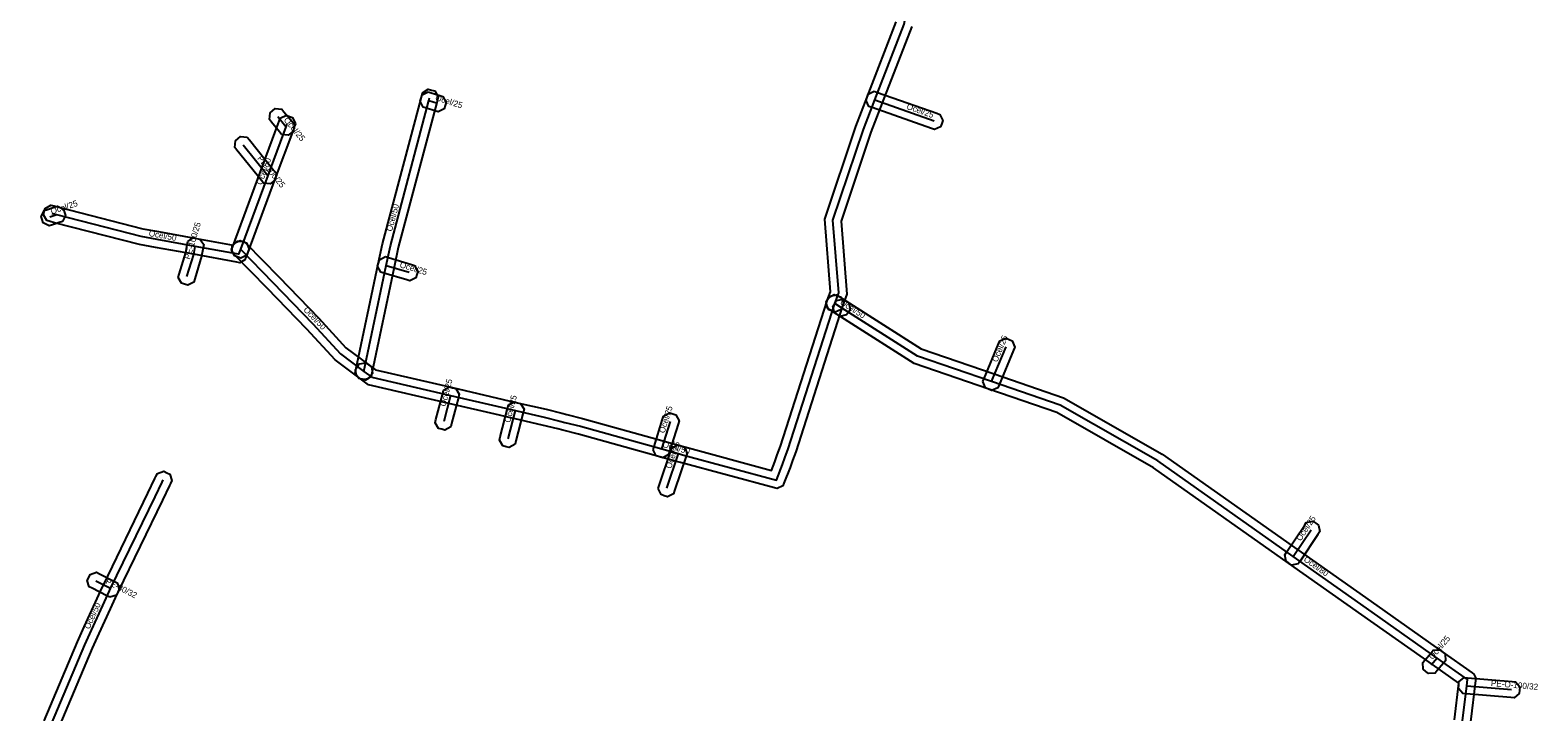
# Model space of a CAD drawing. Extents: x -569373 to -565022, y -1135090 to -1131496.
# Drawn here: x -565423.2 to -565236.8, y -1133846.6 to -1133762.4 of the extents above; entities that cross this region are included whole.
import ezdxf

# ---------------------------------------------------------------- set-up
doc = ezdxf.new("R2010")
doc.units = 0
for name, color, linetype in [('1', 7, 'Continuous'), ('24', 7, 'Continuous'), ('30', 7, 'Continuous')]:
    doc.layers.add(name, color=color, linetype=linetype)

msp = doc.modelspace()

# ---------------------------------------------------------------- linework, layer by layer
at = {"layer": '1'}
for points in [[(-565314.174, -1133761.894), (-565317.838, -1133771.351), (-565319.239, -1133774.97), (-565322.927, -1133785.974), (-565322.216, -1133794.98), (-565322.772, -1133796.486), (-565322.915, -1133796.875), (-565323.667, -1133797.221), (-565324.056, -1133797.078), (-565324.445, -1133796.935), (-565324.791, -1133796.183), (-565324.648, -1133795.794), (-565324.244, -1133794.7), (-565324.953, -1133785.726), (-565321.121, -1133774.29), (-565319.702, -1133770.629), (-565316.106, -1133761.346)], [(-565247.112, -1133847.641), (-565246.573, -1133843.104), (-565249.827, -1133840.807), (-565258.586, -1133834.627), (-565267.617, -1133828.257), (-565284.337, -1133816.455), (-565296.284, -1133809.645), (-565304.656, -1133806.755), (-565313.917, -1133803.567), (-565323.407, -1133797.523), (-565323.757, -1133797.301), (-565323.936, -1133796.492), (-565323.713, -1133796.143), (-565323.491, -1133795.793), (-565322.682, -1133795.614), (-565322.333, -1133795.837), (-565313.043, -1133801.753), (-565304.004, -1133804.865), (-565295.456, -1133807.815), (-565283.263, -1133814.765), (-565266.463, -1133826.623), (-565257.434, -1133832.993), (-565248.673, -1133839.173), (-565244.933, -1133841.813), (-565244.708, -1133841.972), (-565244.485, -1133842.474), (-565244.517, -1133842.748), (-565245.126, -1133847.877)], [(-565421.442, -1133847.742), (-565417.316, -1133837.968), (-565416.48, -1133836.135), (-565415.08, -1133833.075), (-565414.246, -1133831.246), (-565414.111, -1133830.965), (-565408.61, -1133819.605), (-565407.741, -1133817.806), (-565407.611, -1133817.536), (-565407.431, -1133817.163), (-565406.649, -1133816.889), (-565406.276, -1133817.069), (-565405.903, -1133817.249), (-565405.629, -1133818.031), (-565405.809, -1133818.404), (-565405.939, -1133818.674), (-565406.81, -1133820.475), (-565412.309, -1133831.835), (-565412.434, -1133832.094), (-565413.26, -1133833.905), (-565414.66, -1133836.965), (-565415.484, -1133838.772), (-565419.598, -1133848.518)]]:
    msp.add_lwpolyline(points, dxfattribs=at)
for points in [[(-565382.974, -1133804.75), (-565382.889, -1133804.344), (-565380.129, -1133791.234), (-565379.613, -1133788.779), (-565374.847, -1133770.797), (-565374.768, -1133770.49), (-565374.664, -1133770.089), (-565373.951, -1133769.668), (-565373.55, -1133769.772), (-565373.149, -1133769.876), (-565372.728, -1133770.589), (-565372.832, -1133770.99), (-565372.913, -1133771.303), (-565377.667, -1133789.241), (-565378.171, -1133791.646), (-565380.931, -1133804.756), (-565381.016, -1133805.162), (-565381.71, -1133805.614), (-565382.116, -1133805.529), (-565382.522, -1133805.444)], [(-565373.975, -1133769.972), (-565373.58, -1133770.096), (-565372.53, -1133770.426), (-565372.135, -1133770.55), (-565371.752, -1133771.285), (-565371.876, -1133771.68), (-565372, -1133772.075), (-565372.735, -1133772.458), (-565373.13, -1133772.334), (-565374.18, -1133772.004), (-565374.575, -1133771.88), (-565374.958, -1133771.145), (-565374.834, -1133770.75), (-565374.71, -1133770.355)], [(-565318.828, -1133769.909), (-565318.437, -1133770.047), (-565311.107, -1133772.637), (-565310.716, -1133772.775), (-565310.359, -1133773.522), (-565310.497, -1133773.913), (-565310.635, -1133774.304), (-565311.382, -1133774.661), (-565311.773, -1133774.523), (-565319.103, -1133771.933), (-565319.494, -1133771.795), (-565319.851, -1133771.048), (-565319.713, -1133770.657), (-565319.575, -1133770.266)], [(-565390.368, -1133773.923), (-565390.51, -1133774.312), (-565390.631, -1133774.645), (-565392.862, -1133780.667), (-565396.242, -1133789.797), (-565396.386, -1133790.186), (-565397.138, -1133790.532), (-565397.527, -1133790.388), (-565397.916, -1133790.244), (-565398.262, -1133789.492), (-565398.118, -1133789.103), (-565394.738, -1133779.973), (-565392.509, -1133773.955), (-565392.39, -1133773.628), (-565392.248, -1133773.239), (-565391.497, -1133772.888), (-565391.108, -1133773.03), (-565390.719, -1133773.172)], [(-565392.082, -1133775.254), (-565392.344, -1133774.933), (-565393.334, -1133773.723), (-565393.596, -1133773.402), (-565393.514, -1133772.578), (-565393.193, -1133772.316), (-565392.872, -1133772.054), (-565392.048, -1133772.136), (-565391.786, -1133772.457), (-565390.796, -1133773.667), (-565390.534, -1133773.988), (-565390.616, -1133774.812), (-565390.937, -1133775.074), (-565391.258, -1133775.336)], [(-565396.322, -1133775.6), (-565396.062, -1133775.922), (-565393.022, -1133779.692), (-565392.762, -1133780.015), (-565392.85, -1133780.838), (-565393.172, -1133781.098), (-565393.495, -1133781.358), (-565394.318, -1133781.27), (-565394.578, -1133780.948), (-565397.618, -1133777.178), (-565397.878, -1133776.855), (-565397.79, -1133776.032), (-565397.468, -1133775.772), (-565397.145, -1133775.512)], [(-565419.177, -1133786.023), (-565419.571, -1133786.151), (-565420.401, -1133786.421), (-565420.795, -1133786.549), (-565421.533, -1133786.173), (-565421.661, -1133785.779), (-565421.789, -1133785.385), (-565421.413, -1133784.647), (-565421.019, -1133784.519), (-565420.189, -1133784.249), (-565419.795, -1133784.121), (-565419.057, -1133784.497), (-565418.929, -1133784.891), (-565418.801, -1133785.285)], [(-565402.591, -1133788.106), (-565398.054, -1133788.937), (-565397.963, -1133788.703), (-565397.205, -1133788.367), (-565396.819, -1133788.517), (-565396.433, -1133788.667), (-565396.097, -1133789.425), (-565396.247, -1133789.811), (-565396.487, -1133790.431), (-565396.617, -1133790.767), (-565397.246, -1133791.119), (-565397.6, -1133791.054), (-565402.949, -1133790.074), (-565407.648, -1133789.221), (-565409.654, -1133788.858), (-565420.132, -1133786.168), (-565420.704, -1133786.017), (-565421.105, -1133785.912), (-565421.523, -1133785.197), (-565421.417, -1133784.796), (-565421.312, -1133784.395), (-565420.597, -1133783.977), (-565420.196, -1133784.083), (-565419.628, -1133784.232), (-565409.226, -1133786.902), (-565407.292, -1133787.253)], [(-565404.857, -1133792.926), (-565404.737, -1133792.53), (-565403.924, -1133789.845), (-565403.754, -1133788.911), (-565403.68, -1133788.503), (-565402.999, -1133788.032), (-565402.591, -1133788.106), (-565402.183, -1133788.18), (-565401.712, -1133788.861), (-565401.786, -1133789.269), (-565401.976, -1133790.315), (-565402.823, -1133793.11), (-565402.943, -1133793.506), (-565403.674, -1133793.897), (-565404.07, -1133793.777), (-565404.466, -1133793.657)], [(-565396.756, -1133788.454), (-565396.466, -1133788.75), (-565392.443, -1133792.852), (-565387.493, -1133797.973), (-565384.126, -1133801.616), (-565381.306, -1133803.753), (-565380.976, -1133804.003), (-565380.863, -1133804.824), (-565381.113, -1133805.154), (-565381.363, -1133805.484), (-565382.184, -1133805.597), (-565382.514, -1133805.347), (-565385.474, -1133803.104), (-565388.947, -1133799.347), (-565393.877, -1133794.248), (-565397.894, -1133790.15), (-565398.184, -1133789.854), (-565398.176, -1133789.026), (-565397.88, -1133788.736), (-565397.584, -1133788.446)], [(-565379.258, -1133790.363), (-565378.861, -1133790.483), (-565376.041, -1133791.333), (-565375.645, -1133791.452), (-565375.253, -1133792.182), (-565375.373, -1133792.579), (-565375.492, -1133792.975), (-565376.222, -1133793.367), (-565376.619, -1133793.247), (-565379.439, -1133792.397), (-565379.835, -1133792.278), (-565380.227, -1133791.548), (-565380.107, -1133791.151), (-565379.988, -1133790.755)], [(-565381.657, -1133803.497), (-565381.322, -1133803.741), (-565380.496, -1133804.342), (-565370.973, -1133806.556), (-565364.715, -1133808.016), (-565362.967, -1133808.415), (-565362.765, -1133808.461), (-565359.397, -1133809.237), (-565357.449, -1133809.722), (-565356.827, -1133809.877), (-565354.874, -1133810.363), (-565344.812, -1133813.177), (-565342.752, -1133813.747), (-565342.255, -1133813.886), (-565331.52, -1133816.782), (-565331.1, -1133815.728), (-565330.822, -1133814.882), (-565330.403, -1133813.806), (-565324.663, -1133795.836), (-565324.537, -1133795.441), (-565323.8, -1133795.061), (-565323.406, -1133795.187), (-565323.011, -1133795.313), (-565322.631, -1133796.05), (-565322.757, -1133796.444), (-565328.517, -1133814.474), (-565328.938, -1133815.558), (-565329.22, -1133816.412), (-565329.991, -1133818.35), (-565330.132, -1133818.704), (-565330.813, -1133819.045), (-565331.181, -1133818.945), (-565342.785, -1133815.814), (-565343.288, -1133815.673), (-565345.348, -1133815.103), (-565355.386, -1133812.297), (-565357.311, -1133811.817), (-565357.933, -1133811.662), (-565359.863, -1133811.183), (-565363.213, -1133810.411), (-565363.413, -1133810.365), (-565365.165, -1133809.964), (-565371.427, -1133808.504), (-565381.344, -1133806.198), (-565382.498, -1133805.359), (-565382.833, -1133805.115), (-565382.963, -1133804.297), (-565382.719, -1133803.962), (-565382.475, -1133803.627)], [(-565323.063, -1133797.745), (-565323.411, -1133797.521), (-565324.251, -1133796.981), (-565324.599, -1133796.757), (-565324.775, -1133795.947), (-565324.551, -1133795.599), (-565324.327, -1133795.251), (-565323.517, -1133795.075), (-565323.169, -1133795.299), (-565322.329, -1133795.839), (-565321.981, -1133796.063), (-565321.805, -1133796.873), (-565322.029, -1133797.221), (-565322.253, -1133797.569)], [(-565305.412, -1133805.806), (-565305.253, -1133805.424), (-565303.463, -1133801.144), (-565303.303, -1133800.762), (-565302.536, -1133800.448), (-565302.154, -1133800.607), (-565301.772, -1133800.767), (-565301.458, -1133801.534), (-565301.617, -1133801.916), (-565303.407, -1133806.196), (-565303.567, -1133806.578), (-565304.334, -1133806.892), (-565304.716, -1133806.733), (-565305.098, -1133806.573)], [(-565370.128, -1133807.382), (-565370.233, -1133807.783), (-565371.073, -1133810.993), (-565371.178, -1133811.394), (-565371.892, -1133811.812), (-565372.293, -1133811.707), (-565372.694, -1133811.602), (-565373.112, -1133810.888), (-565373.007, -1133810.487), (-565372.167, -1133807.277), (-565372.062, -1133806.876), (-565371.348, -1133806.458), (-565370.947, -1133806.563), (-565370.546, -1133806.668)], [(-565365.162, -1133813.042), (-565365.058, -1133812.641), (-565364.158, -1133809.141), (-565364.055, -1133808.74), (-565363.342, -1133808.318), (-565362.941, -1133808.422), (-565362.54, -1133808.525), (-565362.118, -1133809.238), (-565362.222, -1133809.639), (-565363.122, -1133813.139), (-565363.225, -1133813.54), (-565363.938, -1133813.962), (-565364.339, -1133813.858), (-565364.74, -1133813.755)], [(-565346.158, -1133814.239), (-565346.035, -1133813.843), (-565344.985, -1133810.463), (-565344.862, -1133810.067), (-565344.129, -1133809.682), (-565343.733, -1133809.805), (-565343.337, -1133809.928), (-565342.952, -1133810.661), (-565343.075, -1133811.057), (-565344.125, -1133814.437), (-565344.248, -1133814.833), (-565344.981, -1133815.218), (-565345.377, -1133815.095), (-565345.773, -1133814.972)], [(-565345.55, -1133819.04), (-565345.417, -1133818.648), (-565343.967, -1133814.388), (-565343.833, -1133813.996), (-565343.09, -1133813.63), (-565342.698, -1133813.763), (-565342.306, -1133813.897), (-565341.94, -1133814.64), (-565342.073, -1133815.032), (-565343.523, -1133819.292), (-565343.657, -1133819.684), (-565344.4, -1133820.05), (-565344.792, -1133819.917), (-565345.184, -1133819.783)], [(-565268.101, -1133827.228), (-565267.871, -1133826.884), (-565265.661, -1133823.584), (-565265.43, -1133823.24), (-565264.618, -1133823.079), (-565264.274, -1133823.309), (-565263.93, -1133823.54), (-565263.769, -1133824.352), (-565263.999, -1133824.696), (-565266.209, -1133827.996), (-565266.44, -1133828.34), (-565267.252, -1133828.501), (-565267.596, -1133828.271), (-565267.94, -1133828.04)], [(-565413.296, -1133832.479), (-565413.665, -1133832.29), (-565415.485, -1133831.36), (-565415.854, -1133831.172), (-565416.109, -1133830.384), (-565415.92, -1133830.015), (-565415.732, -1133829.646), (-565414.944, -1133829.391), (-565414.575, -1133829.58), (-565412.755, -1133830.51), (-565412.386, -1133830.698), (-565412.131, -1133831.486), (-565412.32, -1133831.855), (-565412.508, -1133832.224)], [(-565248.221, -1133840.324), (-565248.49, -1133840.639), (-565249.25, -1133841.529), (-565249.519, -1133841.844), (-565250.344, -1133841.909), (-565250.659, -1133841.64), (-565250.974, -1133841.371), (-565251.039, -1133840.546), (-565250.77, -1133840.231), (-565250.01, -1133839.341), (-565249.741, -1133839.026), (-565248.916, -1133838.961), (-565248.601, -1133839.23), (-565248.286, -1133839.499)], [(-565245.932, -1133842.383), (-565245.519, -1133842.418), (-565239.996, -1133842.884), (-565239.583, -1133842.919), (-565239.049, -1133843.551), (-565239.084, -1133843.964), (-565239.119, -1133844.377), (-565239.751, -1133844.911), (-565240.164, -1133844.876), (-565245.687, -1133844.41), (-565246.1, -1133844.375), (-565246.634, -1133843.743), (-565246.599, -1133843.33), (-565246.564, -1133842.917)]]:
    msp.add_lwpolyline(points, close=True, dxfattribs=at)
at = {"layer": '24'}
for points in [[(-565323.71, -1133796.14), (-565323.23, -1133794.84), (-565323.94, -1133785.85), (-565320.18, -1133774.63), (-565318.77, -1133770.99), (-565315.14, -1133761.62), (-565314.25, -1133756.83), (-565312.98, -1133750.01), (-565321.88, -1133740.73), (-565331.07, -1133737.1), (-565335.14, -1133735.5), (-565338.77, -1133734.06), (-565340.3, -1133733.46), (-565351.18, -1133729.27)], [(-565381.91, -1133804.55), (-565379.15, -1133791.44), (-565378.64, -1133789.01), (-565373.88, -1133771.05), (-565373.8, -1133770.74)], [(-565373.88, -1133771.05), (-565372.83, -1133771.38)], [(-565318.77, -1133770.99), (-565311.44, -1133773.58)], [(-565391.45, -1133773.97), (-565391.57, -1133774.3), (-565393.8, -1133780.32), (-565397.18, -1133789.45)], [(-565391.57, -1133774.3), (-565392.56, -1133773.09)], [(-565396.84, -1133776.55), (-565393.8, -1133780.32)], [(-565419.88, -1133785.2), (-565420.71, -1133785.47)], [(-565397.18, -1133789.45), (-565397.42, -1133790.07), (-565402.77, -1133789.09), (-565407.47, -1133788.237), (-565409.44, -1133787.88), (-565419.88, -1133785.2), (-565420.45, -1133785.05)], [(-565403.78, -1133792.82), (-565402.95, -1133790.08), (-565402.77, -1133789.09)], [(-565397.18, -1133789.45), (-565393.16, -1133793.55), (-565388.22, -1133798.66), (-565384.8, -1133802.36), (-565381.91, -1133804.55)], [(-565379.15, -1133791.44), (-565376.33, -1133792.29)], [(-565381.91, -1133804.55), (-565380.92, -1133805.27), (-565371.2, -1133807.53), (-565364.94, -1133808.99), (-565363.19, -1133809.39), (-565362.989, -1133809.436), (-565359.63, -1133810.21), (-565357.691, -1133810.692), (-565357.069, -1133810.847), (-565355.13, -1133811.33), (-565345.08, -1133814.14), (-565343.02, -1133814.71), (-565342.52, -1133814.85), (-565330.92, -1133817.98), (-565330.16, -1133816.07), (-565329.88, -1133815.22), (-565329.46, -1133814.14), (-565323.71, -1133796.14)], [(-565322.87, -1133796.68), (-565323.71, -1133796.14)], [(-565250.86, -1133882.66), (-565250.236, -1133878.181), (-565249.96, -1133876.2), (-565249.87, -1133875.59), (-565247.48, -1133859.22), (-565246.119, -1133847.759), (-565245.603, -1133843.414), (-565245.51, -1133842.63), (-565249.25, -1133839.99), (-565258.01, -1133833.81), (-565267.04, -1133827.44), (-565283.8, -1133815.61), (-565295.87, -1133808.73), (-565304.33, -1133805.81), (-565313.48, -1133802.66), (-565322.87, -1133796.68)], [(-565304.33, -1133805.81), (-565302.54, -1133801.53)], [(-565371.2, -1133807.53), (-565372.04, -1133810.74)], [(-565364.09, -1133812.89), (-565363.19, -1133809.39)], [(-565345.08, -1133814.14), (-565344.03, -1133810.76)], [(-565344.47, -1133818.97), (-565343.02, -1133814.71)], [(-565422.03, -1133855.52), (-565423.16, -1133854.41), (-565421.294, -1133849.972), (-565420.52, -1133848.13), (-565416.4, -1133838.37), (-565415.57, -1133836.55), (-565414.17, -1133833.49), (-565413.34, -1133831.67), (-565413.21, -1133831.4), (-565407.71, -1133820.04), (-565406.84, -1133818.24), (-565406.71, -1133817.97)], [(-565267.04, -1133827.44), (-565264.83, -1133824.14)], [(-565413.21, -1133831.4), (-565415.03, -1133830.47)], [(-565249.25, -1133839.99), (-565250.01, -1133840.88)], [(-565245.603, -1133843.414), (-565240.08, -1133843.88)]]:
    msp.add_lwpolyline(points, dxfattribs=at)

# ---------------------------------------------------------------- texts
at = {"layer": '30'}
for s, rotation, p in [('Ocel/25', 342.55281, (-565373.155, -1133771.015)), ('Ocel/25', 340.53952, (-565314.905, -1133772.085)), ('Ocel/25', 309.28941, (-565391.865, -1133773.495)), ('Ocel/50', 69.68504, (-565394.532, -1133781.557)), ('PE-100/25', 308.88153, (-565395.12, -1133778.235)), ('Ocel/25', 18.01977, (-565420.495, -1133785.135)), ('Ocel/50', 75.15598, (-565378.44, -1133787.302)), ('PE-100/25', 73.14741, (-565403.419, -1133790.768)), ('Ocel/50', 349.72843, (-565408.544, -1133787.806)), ('Ocel/25', 343.22622, (-565377.54, -1133791.665)), ('Ocel/50', 314.03091, (-565389.44, -1133796.992)), ('Ocel/50', 327.26477, (-565323.132, -1133796.183)), ('Ocel/25', 67.30413, (-565303.635, -1133803.47)), ('Ocel/25', 75.33554, (-565371.82, -1133808.935)), ('Ocel/25', 75.57923, (-565363.84, -1133810.94)), ('Ocel/25', 72.74255, (-565344.755, -1133812.25)), ('Ocel/50', 344.3789, (-565345.061, -1133813.889)), ('Ocel/25', 71.20268, (-565343.945, -1133816.64)), ('Ocel/25', 56.1899, (-565266.135, -1133825.59)), ('Ocel/80', 324.79985, (-565265.83, -1133827.952)), ('PE-80/32', 332.93347, (-565413.92, -1133830.735)), ('Ocel/50', 65.48493, (-565415.833, -1133836.489)), ('Ocel/25', 49.50491, (-565249.83, -1133840.235)), ('PE-O-100/32', 355.17712, (-565242.642, -1133843.447))]:
    msp.add_text(s, height=0.75, rotation=rotation, dxfattribs=at).set_placement(p)

doc.saveas('drawing.dxf')
